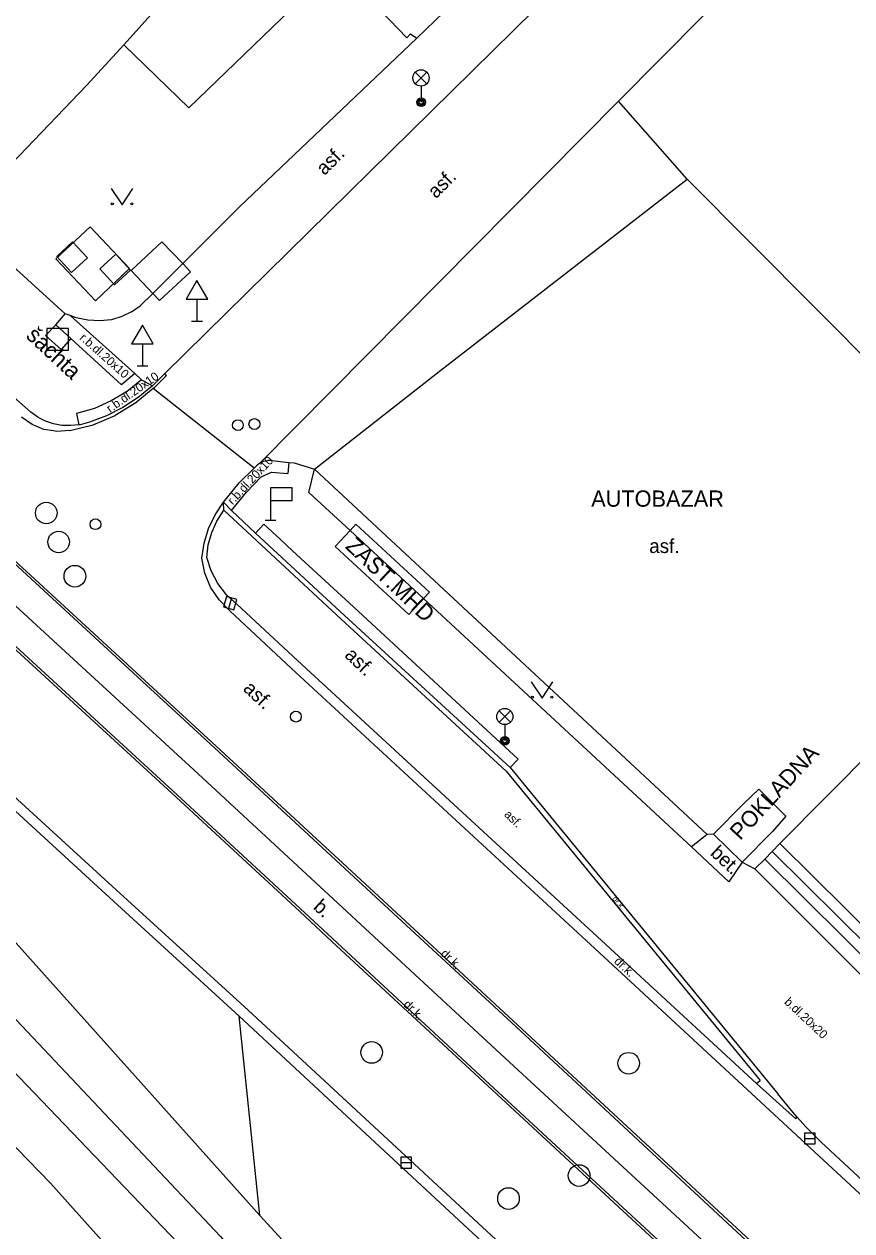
# Model space of a CAD drawing. Extents: x -598932 to -598196, y -1162207 to -1161504.
# Drawn here: x -598817.1 to -598778.9, y -1161799.2 to -1161743.4 of the extents above; entities that cross this region are included whole.
import ezdxf

# ---------------------------------------------------------------- set-up
doc = ezdxf.new("R2010")
doc.units = 0
for name, color, linetype in [('Level 26', 7, 'Continuous'), ('Level 27', 7, 'Continuous'), ('Level 31', 7, 'Continuous'), ('Level 33', 7, 'Continuous'), ('Level 34', 7, 'Continuous'), ('Level 36', 7, 'Continuous'), ('specificka linie pasportu komunikaci', 7, 'Continuous'), ('teplovod - povrch.  znaky - skut. velikost', 7, 'Continuous'), ('TM - budovy zdene_ betonove - VP', 7, 'Continuous'), ('TM - CD - osa koleji', 7, 'Continuous'), ('TM - chodniky - VP', 7, 'Continuous'), ('TM - hladina vodniho toku_ bazenu_ nadrze', 7, 'Continuous'), ('TM - horni hrana svahu', 7, 'Continuous'), ('TM - komunikace - VP', 7, 'Continuous'), ('TM - letecke snimky - pomocna linie', 7, 'Continuous'), ('TM - plot dreveny_ kovovy - VP', 7, 'Continuous'), ('TM - popis objektu', 7, 'Continuous'), ('TM - popis povrchu', 7, 'Continuous'), ('TM - poznamka', 7, 'Continuous'), ('TM - pristresek', 7, 'Continuous'), ('TM - rozhrani mezi zpev. plochami mezi sebou - VP', 7, 'Continuous'), ('TM - rozhrani ploch obecne - NP', 7, 'Continuous'), ('TM - rozhrani ploch obecne - VP', 7, 'Continuous'), ('TM - schody - VP', 7, 'Continuous'), ('TM - vjezd na pozemek', 7, 'Continuous'), ('TM - zabradli - VP', 7, 'Continuous')]:
    doc.layers.add(name, color=color, linetype=linetype)

msp = doc.modelspace()

# ---------------------------------------------------------------- linework, layer by layer
at = {"layer": 'Level 26'}
for points in [[(-598814.937, -1161754.867), (-598814.203, -1161754.187), (-598814.883, -1161753.453), (-598815.617, -1161754.133)], [(-598812.947, -1161755.437), (-598812.213, -1161754.757), (-598812.893, -1161754.023), (-598813.627, -1161754.703)], [(-598816.07, -1161758.45), (-598815.07, -1161758.45), (-598815.07, -1161757.45), (-598816.07, -1161757.45)]]:
    msp.add_lwpolyline(points, close=True, dxfattribs=at)
at = {"layer": 'Level 27'}
for p, q in [((-598807.538, -1161769.91), (-598807.682, -1161770.39)), ((-598781.08, -1161794.89), (-598780.58, -1161794.89)), ((-598799.73, -1161796), (-598799.23, -1161796))]:
    msp.add_line(p, q, dxfattribs=at)
for points in [[(-598807.778, -1161769.839), (-598807.921, -1161770.318), (-598807.442, -1161770.461), (-598807.299, -1161769.982)], [(-598781.08, -1161795.14), (-598780.58, -1161795.14), (-598780.58, -1161794.64), (-598781.08, -1161794.64)], [(-598799.73, -1161796.25), (-598799.23, -1161796.25), (-598799.23, -1161795.75), (-598799.73, -1161795.75)]]:
    msp.add_lwpolyline(points, close=True, dxfattribs=at)
for centre in [(-598816.1, -1161765.98), (-598815.53, -1161767.32), (-598814.78, -1161768.9), (-598801.07, -1161790.91), (-598789.2, -1161791.41), (-598791.49, -1161796.6), (-598794.75, -1161797.66)]:
    msp.add_circle(centre, 0.5, dxfattribs=at)
at = {"layer": 'Level 31'}
for centre in [(-598807.25, -1161761.92), (-598806.49, -1161761.87), (-598813.83, -1161766.5), (-598804.57, -1161775.39)]:
    msp.add_circle(centre, 0.25, dxfattribs=at)
at = {"layer": 'Level 33'}
for p, q in [((-598799.055, -1161746.14), (-598798.525, -1161745.61)), ((-598799.055, -1161745.61), (-598798.525, -1161746.14)), ((-598798.79, -1161746.25), (-598798.79, -1161747)), ((-598795.185, -1161775.65), (-598794.655, -1161775.12)), ((-598795.185, -1161775.12), (-598794.655, -1161775.65)), ((-598794.92, -1161775.76), (-598794.92, -1161776.51))]:
    msp.add_line(p, q, dxfattribs=at)
for centre, radius in [((-598798.79, -1161745.875), 0.375), ((-598798.79, -1161747), 0.2), ((-598798.79, -1161747), 0.145), ((-598798.79, -1161747), 0.0876), ((-598794.92, -1161775.385), 0.375), ((-598794.92, -1161776.51), 0.2), ((-598794.92, -1161776.51), 0.145), ((-598794.92, -1161776.51), 0.0876)]:
    msp.add_circle(centre, radius, dxfattribs=at)
at = {"layer": 'Level 34'}
for p, q in [((-598809.14, -1161756.102), (-598809.14, -1161757.12)), ((-598809.39, -1161757.12), (-598808.89, -1161757.12)), ((-598811.66, -1161758.162), (-598811.66, -1161759.18)), ((-598811.91, -1161759.18), (-598811.41, -1161759.18)), ((-598805.74, -1161765.41), (-598805.74, -1161766.31)), ((-598805.99, -1161766.31), (-598805.49, -1161766.31))]:
    msp.add_line(p, q, dxfattribs=at)
for points in [[(-598809.64, -1161756.102), (-598808.64, -1161756.102), (-598809.14, -1161755.236)], [(-598812.16, -1161758.162), (-598811.16, -1161758.162), (-598811.66, -1161757.296)], [(-598805.74, -1161765.41), (-598804.74, -1161765.41), (-598804.74, -1161764.81), (-598805.74, -1161764.81)]]:
    msp.add_lwpolyline(points, close=True, dxfattribs=at)
at = {"layer": 'Level 36'}
for points in [[(-598813.1, -1161750.99), (-598812.6, -1161751.74), (-598812.1, -1161750.99)], [(-598793.7, -1161773.79), (-598793.2, -1161774.54), (-598792.7, -1161773.79)]]:
    msp.add_lwpolyline(points, dxfattribs=at)
for centre in [(-598813.05, -1161751.69), (-598812.151, -1161751.69), (-598793.65, -1161774.49), (-598792.751, -1161774.49)]:
    msp.add_circle(centre, 0.05, dxfattribs=at)
at = {"layer": 'specificka linie pasportu komunikaci'}
for points in [[(-598789.67, -1161746.95), (-598806.24, -1161763.67)], [(-598806.5, -1161763.91), (-598811.16, -1161760.22)], [(-598806.23, -1161798.45), (-598807.19, -1161789.23)], [(-598783.29, -1161792.35), (-598781.48, -1161793.97)], [(-598781.48, -1161793.97), (-598781.41, -1161793.9)]]:
    msp.add_lwpolyline(points, dxfattribs=at)
at = {"layer": 'teplovod - povrch.  znaky - skut. velikost'}
for points in [[(-598812.18, -1161754.77), (-598810.76, -1161753.45), (-598809.8, -1161754.45)], [(-598809.8, -1161754.45), (-598809.44, -1161754.83), (-598810.87, -1161756.16), (-598811.18, -1161755.83)], [(-598811.18, -1161755.83), (-598812.18, -1161754.77)]]:
    msp.add_lwpolyline(points, dxfattribs=at)
at = {"layer": 'TM - budovy zdene_ betonove - VP'}
for points in [[(-598802.68, -1161740.64), (-598809.51, -1161747.26)], [(-598812.52, -1161744.34), (-598810.7, -1161742.32)], [(-598812.52, -1161744.34), (-598814.25, -1161746.23)], [(-598809.51, -1161747.26), (-598812.52, -1161744.34)], [(-598814.25, -1161746.23), (-598820.13, -1161752.35)], [(-598769.17, -1161768.11), (-598782.22, -1161781.26)], [(-598785.28, -1161780.82), (-598783.88, -1161779.4)], [(-598783.96, -1161782.12), (-598782.56, -1161780.7)], [(-598783.96, -1161782.12), (-598785.28, -1161780.82)], [(-598782.22, -1161781.26), (-598773.09, -1161790.29)]]:
    msp.add_lwpolyline(points, dxfattribs=at)
at = {"layer": 'TM - CD - osa koleji'}
msp.add_lwpolyline([(-598823.67, -1161764.63), (-598809.08, -1161778.04), (-598795.12, -1161790.98), (-598780.98, -1161804.03), (-598752.01, -1161830.97), (-598740.39, -1161841.76), (-598737.43, -1161844.53), (-598720.51, -1161860.13)], dxfattribs=at)
at = {"layer": 'TM - chodniky - VP'}
for points in [[(-598802.68, -1161740.64), (-598799.44, -1161744.02), (-598799.28, -1161743.84), (-598798.98, -1161744.03)], [(-598802.07, -1161766.79), (-598803.98, -1161765.03), (-598803.71, -1161763.96)], [(-598798.67, -1161769.93), (-598802.07, -1161766.79)], [(-598786.3, -1161781.4), (-598798.67, -1161769.93)], [(-598785.57, -1161780.84), (-598786.3, -1161781.4)]]:
    msp.add_lwpolyline(points, dxfattribs=at)
at = {"layer": 'TM - hladina vodniho toku_ bazenu_ nadrze'}
msp.add_lwpolyline([(-598720.27, -1161904.76), (-598749.26, -1161871.38), (-598790.83, -1161824.98), (-598815.91, -1161796.95), (-598834.93, -1161777.35), (-598836.37, -1161776.01), (-598850.71, -1161762.63), (-598866.62, -1161749.21), (-598892.99, -1161728.98)], dxfattribs=at)
at = {"layer": 'TM - horni hrana svahu'}
for points in [[(-598932.017, -1161697.604), (-598929.76, -1161698.95), (-598888.91, -1161727.38), (-598861.19, -1161748.52), (-598845.68, -1161761.08), (-598825.16, -1161781.28), (-598808.06, -1161799.42), (-598788.14, -1161822.37), (-598765.72, -1161848.31), (-598730.99, -1161888.48), (-598729.85, -1161889.88)], [(-598792.56, -1161813.35), (-598806.23, -1161798.45)]]:
    msp.add_lwpolyline(points, dxfattribs=at)
at = {"layer": 'TM - komunikace - VP'}
for points in [[(-598816.81, -1161761.32), (-598817.6, -1161760.62), (-598818.96, -1161759.43), (-598836.26, -1161743.96), (-598839.2, -1161741.39)], [(-598810.63, -1161759.54), (-598792.63, -1161741.81)], [(-598845.59, -1161754.76), (-598845.41, -1161754.57), (-598828.96, -1161769.3), (-598822.48, -1161775.21), (-598822.95, -1161775.76), (-598822.6, -1161776.07), (-598822.11, -1161775.55), (-598813.72, -1161783.25), (-598807.19, -1161789.23)], [(-598810.63, -1161759.54), (-598811.2, -1161760.1)], [(-598811.2, -1161760.1), (-598811.86, -1161760.64), (-598812.56, -1161761.1), (-598813.32, -1161761.49)], [(-598815.39, -1161761.93), (-598815.77, -1161761.86), (-598816.14, -1161761.73), (-598816.38, -1161761.61), (-598816.49, -1161761.55), (-598816.81, -1161761.32)], [(-598814.11, -1161761.79), (-598814.53, -1161761.9), (-598814.59, -1161761.91), (-598814.96, -1161761.94), (-598815.39, -1161761.93)], [(-598813.32, -1161761.49), (-598814.11, -1161761.79)], [(-598807.19, -1161764.59), (-598806.5, -1161763.91), (-598806.39, -1161763.8)], [(-598806.24, -1161763.67), (-598806.39, -1161763.8)], [(-598806.24, -1161763.67), (-598806.06, -1161763.58), (-598805.86, -1161763.55)], [(-598805.66, -1161763.56), (-598805.86, -1161763.55)], [(-598805.66, -1161763.56), (-598804.89, -1161763.64), (-598804.65, -1161763.66), (-598803.71, -1161763.96)], [(-598807.91, -1161765.48), (-598807.19, -1161764.59)], [(-598806.44, -1161766.91), (-598807.54, -1161765.86), (-598807.91, -1161765.48)], [(-598794.68, -1161777.74), (-598802.32, -1161770.71), (-598806.44, -1161766.91)], [(-598794.68, -1161777.74), (-598782.31, -1161792.82)], [(-598791.43, -1161803.89), (-598807.19, -1161789.23)], [(-598780.31, -1161795.05), (-598781.01, -1161794.34), (-598781.41, -1161793.9), (-598781.68, -1161793.59), (-598782.31, -1161792.82)], [(-598780.31, -1161795.05), (-598767.93, -1161806.55), (-598756.48, -1161817.3), (-598742.56, -1161830.25), (-598726.93, -1161844.8)]]:
    msp.add_lwpolyline(points, dxfattribs=at)
at = {"layer": 'TM - letecke snimky - pomocna linie'}
for points in [[(-598789.67, -1161746.95), (-598762.51, -1161719.54)], [(-598786.49, -1161750.55), (-598789.67, -1161746.95)], [(-598807.9, -1161765.85), (-598807.91, -1161765.48)], [(-598832, -1161776.77), (-598807.26, -1161802.61)], [(-598783.88, -1161779.4), (-598783.19, -1161778.74), (-598781.94, -1161779.99), (-598782.56, -1161780.7)]]:
    msp.add_lwpolyline(points, dxfattribs=at)
at = {"layer": 'TM - plot dreveny_ kovovy - VP'}
for points in [[(-598798.98, -1161744.03), (-598807.17, -1161751.83)], [(-598797.88, -1161759.38), (-598786.49, -1161750.55)], [(-598786.49, -1161750.55), (-598774.62, -1161762.49)], [(-598809.8, -1161754.45), (-598807.17, -1161751.83)], [(-598819.24, -1161753.13), (-598815.23, -1161756.78)], [(-598811.18, -1161755.83), (-598809.8, -1161754.45)], [(-598811.76, -1161756.4), (-598811.18, -1161755.83)], [(-598814.18, -1161757.07), (-598814.72, -1161756.96), (-598815, -1161756.86), (-598815.23, -1161756.78)], [(-598812.17, -1161756.69), (-598812.61, -1161756.9), (-598813.09, -1161757.05)], [(-598812.17, -1161756.69), (-598811.76, -1161756.4)], [(-598813.09, -1161757.05), (-598813.63, -1161757.1), (-598814.18, -1161757.07)], [(-598785.28, -1161780.82), (-598785.57, -1161780.84), (-598803.71, -1161763.96)], [(-598783.96, -1161782.12), (-598783.37, -1161782.43)]]:
    msp.add_lwpolyline(points, dxfattribs=at)
at = {"layer": 'TM - pristresek'}
for points in [[(-598802.75, -1161767.53), (-598802.07, -1161766.79)], [(-598802.07, -1161766.79), (-598801.8, -1161766.5)], [(-598801.8, -1161766.5), (-598798.4, -1161769.64), (-598798.67, -1161769.93)], [(-598802.75, -1161767.53), (-598799.35, -1161770.67)], [(-598798.67, -1161769.93), (-598799.35, -1161770.67)]]:
    msp.add_lwpolyline(points, dxfattribs=at)
at = {"layer": 'TM - rozhrani mezi zpev. plochami mezi sebou - VP'}
for points in [[(-598839.9, -1161748.14), (-598822.75, -1161763.56), (-598808.13, -1161777.02)], [(-598839.8, -1161748.08), (-598822.68, -1161763.48), (-598808.05, -1161776.94)], [(-598841.73, -1161750.36), (-598825.23, -1161765.21), (-598810.12, -1161779.09)], [(-598841.63, -1161750.3), (-598825.16, -1161765.13), (-598810.05, -1161779.01), (-598804.38, -1161784.26)], [(-598845.05, -1161754.27), (-598828.66, -1161768.95), (-598813.4, -1161782.91), (-598806.77, -1161788.96)], [(-598815.66, -1161757.29), (-598815.23, -1161756.78)], [(-598815, -1161756.86), (-598812.01, -1161759.54), (-598812.63, -1161760.05), (-598814.96, -1161757.92)], [(-598812.01, -1161759.54), (-598811.71, -1161759.82)], [(-598810.55, -1161759.63), (-598810.63, -1161759.54)], [(-598811.71, -1161759.82), (-598812.37, -1161760.36), (-598813.1, -1161760.8), (-598813.88, -1161761.15), (-598814.7, -1161761.38)], [(-598811.71, -1161759.82), (-598811.2, -1161760.1)], [(-598810.55, -1161759.63), (-598811.12, -1161760.19), (-598811.16, -1161760.22)], [(-598811.16, -1161760.22), (-598811.97, -1161760.89), (-598812.92, -1161761.47)], [(-598815.76, -1161762.19), (-598816.21, -1161762.12), (-598816.76, -1161761.89), (-598817.25, -1161761.55)], [(-598814.7, -1161761.38), (-598814.59, -1161761.91)], [(-598813.94, -1161761.9), (-598812.92, -1161761.47)], [(-598815.02, -1161762.17), (-598815.62, -1161762.21), (-598815.76, -1161762.19)], [(-598815.02, -1161762.17), (-598813.94, -1161761.9)], [(-598804.89, -1161763.64), (-598804.94, -1161764.16)], [(-598807.54, -1161765.86), (-598806.85, -1161765.02), (-598806.17, -1161764.31), (-598805.7, -1161764.1), (-598804.94, -1161764.16)], [(-598808.91, -1161768.07), (-598808.81, -1161767.37), (-598808.61, -1161766.7), (-598808.3, -1161766.06), (-598807.91, -1161765.48)], [(-598808.68, -1161768.04), (-598808.62, -1161767.45), (-598808.46, -1161766.88), (-598808.22, -1161766.35), (-598807.9, -1161765.85)], [(-598802.48, -1161770.88), (-598807.9, -1161765.85)], [(-598806.44, -1161766.91), (-598806.05, -1161766.49)], [(-598806.05, -1161766.49), (-598805.3, -1161767.19), (-598804.72, -1161767.73), (-598801.9, -1161770.33), (-598794.31, -1161777.35), (-598794.68, -1161777.74)], [(-598807.63, -1161770.5), (-598808.12, -1161770), (-598808.51, -1161769.41), (-598808.78, -1161768.76), (-598808.8, -1161768.68), (-598808.91, -1161768.07)], [(-598807.3, -1161770.2), (-598807.78, -1161769.76), (-598808.18, -1161769.24), (-598808.48, -1161768.66), (-598808.68, -1161768.04)], [(-598807.63, -1161770.5), (-598804.78, -1161773.16), (-598790.76, -1161786.11), (-598776.47, -1161799.34), (-598761.8, -1161812.95), (-598747.67, -1161826.17), (-598733.02, -1161839.81), (-598718.51, -1161853.3), (-598715.9, -1161855.73), (-598707.31, -1161863.72)], [(-598783.29, -1161792.35), (-598790.45, -1161785.73), (-598804.49, -1161772.8), (-598807.3, -1161770.2)], [(-598794.86, -1161777.91), (-598802.48, -1161770.88)], [(-598802.31, -1161782.41), (-598808.13, -1161777.02)], [(-598808.05, -1161776.94), (-598802.2, -1161782.35)], [(-598794.86, -1161777.91), (-598789.34, -1161784.63), (-598783.12, -1161792.21)], [(-598810.12, -1161779.09), (-598804.39, -1161784.4)], [(-598784.58, -1161783.02), (-598786.3, -1161781.4)], [(-598758.89, -1161822.69), (-598765.45, -1161816.6), (-598780.07, -1161803.03), (-598794.2, -1161789.91), (-598802.31, -1161782.41)], [(-598802.2, -1161782.35), (-598794.12, -1161789.83), (-598779.99, -1161802.95), (-598765.37, -1161816.52), (-598758.81, -1161822.61)], [(-598783.96, -1161782.12), (-598784.58, -1161783.02)], [(-598804.39, -1161784.4), (-598802.91, -1161785.78), (-598796.12, -1161792.07), (-598781.97, -1161805.17)], [(-598804.38, -1161784.26), (-598796.05, -1161791.99), (-598781.9, -1161805.09)], [(-598806.77, -1161788.96), (-598791.18, -1161803.4), (-598770.01, -1161823.1), (-598754.95, -1161837.06)], [(-598783.29, -1161792.35), (-598783.12, -1161792.21)]]:
    msp.add_lwpolyline(points, dxfattribs=at)
at = {"layer": 'TM - rozhrani ploch obecne - NP'}
for points in [[(-598814.08, -1161752.75), (-598815.66, -1161754.23)], [(-598812.26, -1161754.68), (-598814.08, -1161752.75)], [(-598815.66, -1161754.23), (-598813.82, -1161756.18)], [(-598813.82, -1161756.18), (-598812.26, -1161754.68)]]:
    msp.add_lwpolyline(points, dxfattribs=at)
at = {"layer": 'TM - rozhrani ploch obecne - VP'}
for points in [[(-598798.98, -1161744.03), (-598797.74, -1161742.83)], [(-598816.13, -1161757.78), (-598815.66, -1161757.29)], [(-598815.66, -1161757.29), (-598814.96, -1161757.92)], [(-598815.42, -1161758.43), (-598816.13, -1161757.78)], [(-598814.96, -1161757.92), (-598815.42, -1161758.43)], [(-598782.22, -1161781.26), (-598782.57, -1161781.62)], [(-598782.57, -1161781.62), (-598782.91, -1161781.97)], [(-598782.91, -1161781.97), (-598783.37, -1161782.43)]]:
    msp.add_lwpolyline(points, dxfattribs=at)
at = {"layer": 'TM - schody - VP'}
for points in [[(-598782.57, -1161781.62), (-598773.43, -1161790.68)], [(-598782.91, -1161781.97), (-598773.77, -1161791.05)]]:
    msp.add_lwpolyline(points, dxfattribs=at)
at = {"layer": 'TM - vjezd na pozemek'}
for points in [[(-598803.71, -1161763.96), (-598797.88, -1161759.38)], [(-598783.37, -1161782.43), (-598774.23, -1161791.57)]]:
    msp.add_lwpolyline(points, dxfattribs=at)
at = {"layer": 'TM - zabradli - VP'}
for points in [[(-598806.23, -1161798.45), (-598821.96, -1161780.88), (-598834.52, -1161768.12), (-598854.43, -1161750.62)], [(-598792.56, -1161813.35), (-598806.23, -1161798.45)]]:
    msp.add_lwpolyline(points, dxfattribs=at)

# ---------------------------------------------------------------- texts
at = {"layer": 'TM - popis objektu'}
msp.add_text('AUTOBAZAR', height=0.75, dxfattribs=at).set_placement((-598790.93, -1161765.69))
for s, rotation, p in [('ZAST.MHD', 316.75, (-598802.33, -1161767.57)), ('POKLADNA', 47.3986, (-598784.05, -1161781.14))]:
    msp.add_text(s, height=0.75, rotation=rotation, dxfattribs=at).set_placement(p)
at = {"layer": 'TM - popis povrchu'}
for s, height, rotation, p in [('asf.', 0.65, 45, (-598803.25, -1161750.41)), ('asf.', 0.65, 45, (-598798.1, -1161751.48)), ('r.b.dl.20x10', 0.4, 318.2925, (-598814.59, -1161757.93)), ('r.b.dl.20x10', 0.4, 35, (-598813.15, -1161761.36)), ('r.b.dl.20x10', 0.4, 47, (-598807.49, -1161765.63)), ('asf.', 0.65, 316.3871, (-598802.36, -1161772.6)), ('asf.', 0.65, 317, (-598807.05, -1161774.15)), ('asf.', 0.4, 315.8498, (-598794.98, -1161779.95)), ('bet.', 0.65, 317.075, (-598785.47, -1161781.75)), ('b.', 0.65, 317.28, (-598803.81, -1161784.24)), ('dr.k.', 0.25, 309.6576, (-598789.97, -1161783.82)), ('dr.k.', 0.4, 316.2403, (-598797.91, -1161786.38)), ('dr.k.', 0.4, 316.9544, (-598789.9, -1161786.74)), ('dr.k.', 0.4, 316.2403, (-598799.64, -1161788.73)), ('b.dl.20x20', 0.4, 316.7802, (-598782.04, -1161788.62))]:
    msp.add_text(s, height=height, rotation=rotation, dxfattribs=at).set_placement(p)
msp.add_text('asf.', height=0.65, dxfattribs=at).set_placement((-598788.25, -1161767.83))
at = {"layer": 'TM - poznamka'}
msp.add_text('šachta', height=0.75, rotation=316.8828, dxfattribs=at).set_placement((-598817.08, -1161757.84))

doc.saveas('drawing.dxf')
